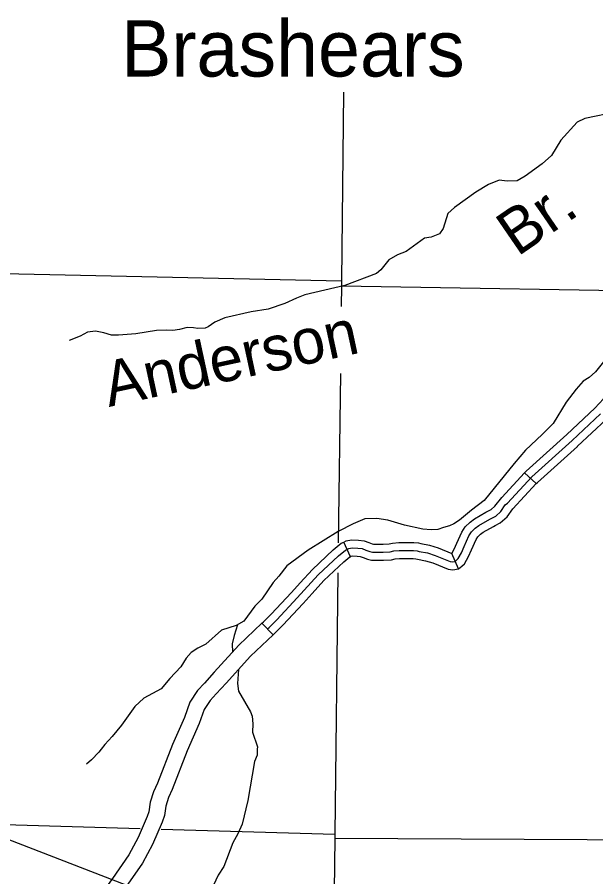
# Model space of a CAD drawing. Extents: x 0 to 3171, y 0 to 2059.
# Drawn here: x 1303 to 1393.3, y 322.5 to 456.7 of the extents above; entities that cross this region are included whole.
import ezdxf

# ---------------------------------------------------------------- set-up
doc = ezdxf.new("R2010")
doc.units = 0
for name, color, linetype in [('Default', 7, 'Continuous'), ('Level 24', 7, 'Continuous'), ('Level 35', 7, 'Continuous'), ('Level 4', 7, 'Continuous'), ('Level 45', 7, 'Continuous'), ('Level 46', 7, 'Continuous'), ('Level 5', 7, 'Continuous')]:
    doc.layers.add(name, color=color, linetype=linetype)

msp = doc.modelspace()

# ---------------------------------------------------------------- linework, layer by layer
at = {"layer": 'Default'}
for p in [(990.73, 447.98), (1029.42, 433.09)]:
    msp.add_line(p, (1391.7, 293.66), dxfattribs=at)
at = {"layer": 'Level 35'}
for points in [[(1396.63, 441.93), (1391.59, 440.91), (1390.39, 440.34), (1387.85, 437.54), (1386.36, 435.12), (1384.93, 433.8), (1382.25, 431.88), (1381.02, 431.18), (1379.46, 431.13), (1378.22, 431.26), (1376.54, 430.59), (1374.54, 429.42), (1371.22, 426.98), (1370.19, 426.06), (1369.47, 423.75), (1368.91, 422.91), (1367.57, 422.39), (1366.54, 422.23), (1363.71, 420.12), (1362.32, 419.59), (1361, 418.85), (1359.76, 417.27), (1359.04, 416.68), (1354.13, 414.82), (1347.89, 413.39), (1346.57, 412.87), (1344.77, 411.99), (1342.17, 411.14), (1339.52, 410.69), (1335.4, 409.8), (1333.81, 409.11), (1332.81, 408.36), (1332.3, 408.14), (1331.18, 408.09), (1330.52, 408.23), (1329.5, 408.28), (1328.29, 407.95), (1327.28, 407.78), (1326.25, 407.87), (1324.71, 407.8), (1321.49, 407.3), (1318.77, 407.05), (1317.69, 407.07), (1316.52, 407.42), (1315.19, 407.7), (1313.98, 407.55), (1312.82, 406.92), (1311.09, 406.24)], [(1412.77, 418.82), (1411.89, 418.59), (1409.92, 417.95), (1408.67, 417.28), (1407.09, 415.48), (1404.68, 414.73), (1403.63, 413.31), (1402.99, 411.92), (1402.06, 410.42), (1400.52, 408.92), (1397.32, 406.09), (1395.55, 404.2), (1393.22, 401.35), (1392.24, 400.47), (1391.33, 399.89), (1390.2, 398.63), (1388.65, 396.59), (1386.65, 393.29), (1384.92, 391.57)], [(1384.92, 391.57), (1382.29, 389.1), (1380.55, 387.02), (1375.86, 381.26), (1373.91, 379.74), (1372.01, 378.21), (1371.14, 377.62), (1370.43, 377.29), (1369.52, 377.02), (1368.64, 376.74)], [(1368.64, 376.74), (1368.61, 376.74), (1367.58, 376.67), (1366.27, 376.77), (1363.43, 377.41), (1360.81, 378.18), (1359.11, 378.43), (1357.26, 378.39), (1355.41, 377.63), (1353.07, 376.43), (1348.37, 373.53), (1345.07, 371.05), (1343.83, 369.47), (1342.93, 368.45), (1341.17, 365.85), (1340.09, 364.78), (1338.34, 362.44), (1337.17, 361.72), (1334.86, 361.02), (1332.4, 358.82), (1331.16, 358.21), (1330.16, 357.51), (1329.37, 356.63), (1328.51, 355.3), (1326.79, 353.45), (1325.47, 351.88), (1322.76, 350.39), (1321.34, 349.12), (1319.25, 346.21), (1317.83, 344.44), (1316.64, 343.14), (1316.11, 342.46)], [(1337.35, 361.83), (1336.83, 360.19), (1336.55, 358.9), (1336.57, 357.56)], [(1337.53, 354.9), (1337.39, 352.69), (1337.5, 351.51), (1339.41, 348.26), (1339.64, 347.58), (1339.75, 346.39), (1339.72, 345.09), (1340.47, 342.8), (1340.46, 342.46)], [(1316.11, 342.46), (1315.72, 341.96), (1314.58, 340.76), (1313.79, 340.08)], [(1340.46, 342.46), (1340.44, 341.49), (1340.03, 340.5), (1338.97, 334.4), (1338.1, 330.72), (1337.44, 329.23), (1336.64, 327.8), (1335.23, 324.13), (1334.37, 322.74), (1333.6, 321.21), (1333.09, 319.5)]]:
    msp.add_lwpolyline(points, dxfattribs=at)
at = {"layer": 'Level 4'}
for points in [[(1353.89, 445.01), (1353.6, 415.58), (1353.59, 414.71), (1353.55, 411.56)], [(1353.43, 401.1), (1353.1, 374.65)], [(1353.05, 369.99), (1352.55, 329.16), (1352.54, 328.54), (1351.62, 254.41)]]:
    msp.add_lwpolyline(points, dxfattribs=at)
at = {"layer": 'Level 45'}
for p, q in [((1383.99, 383.9), (1382.15, 385.59)), ((1354.98, 372.49), (1353.95, 374.77)), ((1371.85, 370.57), (1370.84, 373)), ((1342.93, 360.31), (1341.18, 362.1))]:
    msp.add_line(p, q, dxfattribs=at)
for points in [[(1388.76, 391.57), (1388.76, 391.57), (1393.15, 395.68), (1394.51, 397.13), (1394.86, 397.58)], [(1390.43, 389.71), (1390.45, 389.73), (1394.92, 393.91), (1396.41, 395.5), (1396.84, 396.05)], [(1353.13, 372.63), (1354.22, 373.52), (1354.72, 373.74), (1355.26, 373.85), (1356.14, 373.83), (1356.81, 373.74), (1357.41, 373.52), (1358, 373.3), (1358.44, 373.2), (1359.1, 373.18), (1360.11, 373.19), (1361.2, 373.24), (1361.77, 373.39), (1362.59, 373.46), (1363.63, 373.47), (1364.31, 373.45), (1364.83, 373.45), (1365.41, 373.4), (1365.72, 373.32), (1367.01, 373.07), (1368.24, 372.69), (1370.58, 371.76), (1370.97, 371.71), (1371.32, 371.76), (1371.81, 372.18), (1372.31, 373.09), (1372.75, 374.08), (1373.49, 375.73), (1373.89, 376.38), (1374.48, 376.94), (1375.02, 377.36), (1376.72, 378.33), (1377.66, 378.8), (1378.48, 379.54), (1379.15, 380.56), (1379.49, 380.85), (1383.28, 384.97), (1389.61, 390.65), (1394.04, 394.79)], [(1382.15, 385.59), (1382.4, 385.86), (1388.76, 391.57)], [(1383.99, 383.9), (1384.16, 384.08), (1390.43, 389.71)], [(1376.44, 379.58), (1376.95, 379.84), (1377.52, 380.36), (1378.62, 381.75), (1382.15, 385.59)], [(1377.56, 377.35), (1378.38, 377.76), (1379.44, 378.72), (1380.36, 379.94), (1383.99, 383.9)], [(1370.84, 373), (1371.18, 373.64), (1371.61, 374.59), (1372.38, 376.32), (1372.91, 377.17), (1373.66, 377.89), (1374.33, 378.41), (1376.14, 379.43), (1376.44, 379.58)], [(1372.36, 371), (1372.8, 371.38), (1373.43, 372.54), (1373.89, 373.57), (1374.6, 375.15), (1374.87, 375.58), (1375.3, 375.99), (1375.72, 376.32), (1377.31, 377.22), (1377.56, 377.35)], [(1347.17, 368.43), (1349.05, 370.51), (1352.3, 373.57), (1353.56, 374.59), (1353.95, 374.77)], [(1353.95, 374.77), (1354.33, 374.94), (1355.15, 375.11), (1356.23, 375.08), (1357.12, 374.96), (1357.85, 374.69), (1358.36, 374.5), (1358.6, 374.44), (1359.12, 374.43), (1360.08, 374.44), (1361.01, 374.48), (1361.55, 374.62), (1362.53, 374.71), (1363.09, 374.72)], [(1363.09, 374.72), (1363.64, 374.72), (1364.33, 374.7), (1364.88, 374.7), (1365.61, 374.63), (1365.98, 374.54), (1367.31, 374.28), (1368.66, 373.88), (1370.84, 373)], [(1342.05, 361.2), (1342.29, 361.44), (1343.53, 362.65), (1346.7, 366.04), (1349.94, 369.64), (1353.13, 372.63)], [(1349.03, 366.76), (1350.84, 368.76), (1353.95, 371.69), (1354.88, 372.45), (1354.98, 372.49)], [(1354.98, 372.49), (1355.1, 372.55), (1355.37, 372.6), (1356.04, 372.58), (1356.51, 372.52), (1356.97, 372.35), (1357.64, 372.1), (1358.28, 371.95), (1359.08, 371.92), (1360.15, 371.94), (1361.39, 371.99), (1361.98, 372.15), (1362.66, 372.21), (1363.12, 372.22)], [(1363.12, 372.22), (1363.61, 372.22), (1364.29, 372.2), (1364.77, 372.2), (1365.21, 372.16), (1365.45, 372.1), (1366.71, 371.85), (1367.83, 371.51), (1370.26, 370.54), (1370.98, 370.45), (1371.85, 370.57), (1372.36, 371)], [(1341.18, 362.1), (1341.42, 362.33), (1342.64, 363.53), (1345.78, 366.88), (1347.17, 368.43)], [(1342.93, 360.31), (1343.17, 360.54), (1344.42, 361.78), (1347.62, 365.19), (1349.03, 366.76)]]:
    msp.add_lwpolyline(points, dxfattribs=at)
at = {"layer": 'Level 46'}
for points in [[(1341.18, 362.1), (1337.59, 358.69), (1333.73, 354.44), (1332.2, 352.75), (1331.15, 351.58), (1329.94, 349.79), (1329.07, 347.36), (1327.22, 343.15), (1324.87, 337.13), (1324.26, 335.78), (1323.74, 334.14), (1323.51, 332.65), (1323.28, 331.92), (1321.85, 328.67), (1320.39, 325.94), (1317.84, 322.26), (1316.17, 319.94), (1314.93, 318.97), (1312.54, 317.64), (1309.78, 315.97), (1306.37, 313.88), (1305.73, 313.39), (1304.76, 312.39), (1304, 310.91)], [(1342.93, 360.31), (1339.38, 356.94), (1335.58, 352.76), (1334.06, 351.07), (1333.12, 350.04), (1332.19, 348.65), (1331.4, 346.44), (1329.52, 342.19), (1327.17, 336.16), (1326.6, 334.88), (1326.18, 333.56), (1325.96, 332.09), (1325.63, 331.04), (1324.1, 327.57), (1322.52, 324.63), (1319.88, 320.82)]]:
    msp.add_lwpolyline(points, dxfattribs=at)
at = {"layer": 'Level 5'}
for points in [[(1291.25, 416.89), (1353.6, 415.58)], [(1410.07, 413.75), (1409.21, 413.77), (1353.59, 414.71)], [(1292.1, 330.92), (1322.2, 330.05)], [(1325.43, 329.95), (1352.55, 329.16)], [(1352.54, 328.54), (1421.48, 328.19)]]:
    msp.add_lwpolyline(points, dxfattribs=at)

# ---------------------------------------------------------------- texts
at = {"layer": 'Level 24'}
msp.add_text('Brashears', height=8.8, dxfattribs=at).set_placement((1319.19, 447.45))
at = {"layer": 'Level 35'}
for s, rotation, p in [('Br.', 34.4681, (1381.03, 419.24)), ('Anderson', 12.1777, (1317.3, 395.85))]:
    msp.add_text(s, height=7.04, rotation=rotation, dxfattribs=at).set_placement(p)

doc.saveas('drawing.dxf')
